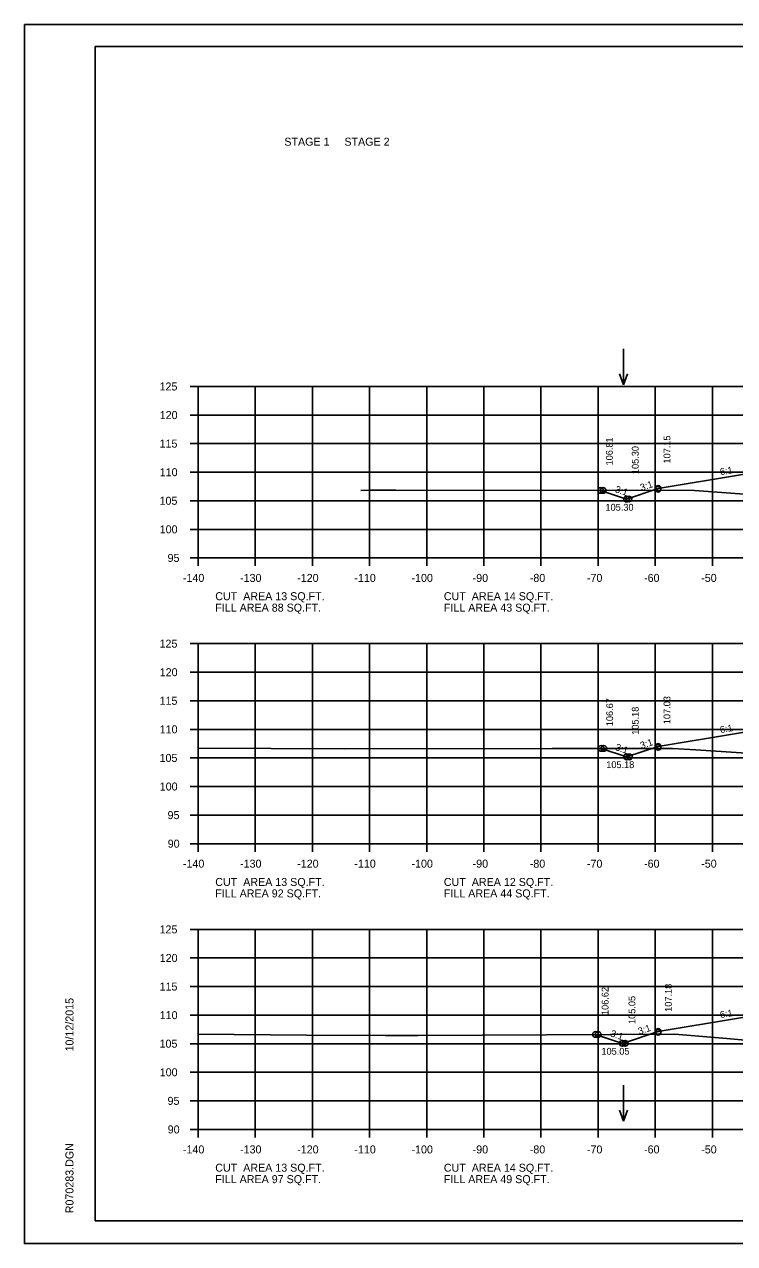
# Model space of a CAD drawing. Extents: x 1175611 to 1176402, y -433344 to -416213.
# Drawn here: x 1175610.6 to 1175734.9, y -425023.4 to -424810 of the extents above; entities that cross this region are included whole.
import ezdxf

# ---------------------------------------------------------------- set-up
doc = ezdxf.new("R2010")
doc.units = 0
for name, color, linetype in [('Default', 7, 'Continuous'), ('R_Axis', 7, 'Continuous'), ('R_Axis Annot', 7, 'Continuous'), ('R_Border', 7, 'Continuous'), ('R_Exist Surface', 7, 'Continuous'), ('R_Fin Surface', 7, 'Continuous'), ('R_Grid', 7, 'Continuous'), ('R_No Plot', 7, 'Continuous'), ('R_Water Annot', 7, 'Continuous'), ('R_Xsect Elev', 7, 'Continuous'), ('R_Xsect Slope', 7, 'Continuous')]:
    doc.layers.add(name, color=color, linetype=linetype)

msp = doc.modelspace()

# ---------------------------------------------------------------- linework, layer by layer
at = {"layer": 'R_Axis'}
for p, q in [((1175639.57, -424873.37), (1175640.97, -424873.37)), ((1175640.97, -424903.37), (1175640.97, -424873.37)), ((1175639.57, -424878.37), (1175640.97, -424878.37)), ((1175639.57, -424883.37), (1175640.97, -424883.37)), ((1175639.57, -424888.37), (1175640.97, -424888.37)), ((1175639.57, -424893.37), (1175640.97, -424893.37)), ((1175639.57, -424898.37), (1175640.97, -424898.37)), ((1175639.57, -424903.37), (1175640.97, -424903.37)), ((1175640.97, -424903.37), (1175920.97, -424903.37)), ((1175640.97, -424904.77), (1175640.97, -424903.37)), ((1175650.97, -424904.77), (1175650.97, -424903.37)), ((1175660.97, -424904.77), (1175660.97, -424903.37)), ((1175670.97, -424904.77), (1175670.97, -424903.37)), ((1175680.97, -424904.77), (1175680.97, -424903.37)), ((1175690.97, -424904.77), (1175690.97, -424903.37)), ((1175700.97, -424904.77), (1175700.97, -424903.37)), ((1175710.97, -424904.77), (1175710.97, -424903.37)), ((1175720.97, -424904.77), (1175720.97, -424903.37)), ((1175730.97, -424904.77), (1175730.97, -424903.37)), ((1175639.57, -424918.37), (1175640.97, -424918.37)), ((1175640.97, -424953.37), (1175640.97, -424918.37)), ((1175639.57, -424923.37), (1175640.97, -424923.37)), ((1175639.57, -424928.37), (1175640.97, -424928.37)), ((1175639.57, -424933.37), (1175640.97, -424933.37)), ((1175639.57, -424938.37), (1175640.97, -424938.37)), ((1175639.57, -424943.37), (1175640.97, -424943.37)), ((1175639.57, -424948.37), (1175640.97, -424948.37)), ((1175639.57, -424953.37), (1175640.97, -424953.37)), ((1175640.97, -424953.37), (1175920.97, -424953.37)), ((1175640.97, -424954.77), (1175640.97, -424953.37)), ((1175650.97, -424954.77), (1175650.97, -424953.37)), ((1175660.97, -424954.77), (1175660.97, -424953.37)), ((1175670.97, -424954.77), (1175670.97, -424953.37)), ((1175680.97, -424954.77), (1175680.97, -424953.37)), ((1175690.97, -424954.77), (1175690.97, -424953.37)), ((1175700.97, -424954.77), (1175700.97, -424953.37)), ((1175710.97, -424954.77), (1175710.97, -424953.37)), ((1175720.97, -424954.77), (1175720.97, -424953.37)), ((1175730.97, -424954.77), (1175730.97, -424953.37)), ((1175639.57, -424968.37), (1175640.97, -424968.37)), ((1175640.97, -425003.37), (1175640.97, -424968.37)), ((1175639.57, -424973.37), (1175640.97, -424973.37)), ((1175639.57, -424978.37), (1175640.97, -424978.37)), ((1175639.57, -424983.37), (1175640.97, -424983.37)), ((1175639.57, -424988.37), (1175640.97, -424988.37)), ((1175639.57, -424993.37), (1175640.97, -424993.37)), ((1175639.57, -424998.37), (1175640.97, -424998.37)), ((1175639.57, -425003.37), (1175640.97, -425003.37)), ((1175640.97, -425003.37), (1175920.97, -425003.37)), ((1175640.97, -425004.77), (1175640.97, -425003.37)), ((1175650.97, -425004.77), (1175650.97, -425003.37)), ((1175660.97, -425004.77), (1175660.97, -425003.37)), ((1175670.97, -425004.77), (1175670.97, -425003.37)), ((1175680.97, -425004.77), (1175680.97, -425003.37)), ((1175690.97, -425004.77), (1175690.97, -425003.37)), ((1175700.97, -425004.77), (1175700.97, -425003.37)), ((1175710.97, -425004.77), (1175710.97, -425003.37)), ((1175720.97, -425004.77), (1175720.97, -425003.37)), ((1175730.97, -425004.77), (1175730.97, -425003.37))]:
    msp.add_line(p, q, dxfattribs=at)
at = {"layer": 'R_Border'}
for p, q in [((1175622.97, -424813.91), (1175939.15, -424813.91)), ((1175622.97, -425019.37), (1175622.97, -424813.91)), ((1175622.97, -425019.37), (1175622.97, -425019.37)), ((1175939.15, -425019.37), (1175622.97, -425019.37))]:
    msp.add_line(p, q, dxfattribs=at)
at = {"layer": 'R_Exist Surface'}
for points in [[(1175669.46, -424891.55), (1175671.18, -424891.52), (1175672.41, -424891.51), (1175675.54, -424891.51), (1175727.83, -424891.58), (1175739.76, -424892.43)], [(1175640.97, -424936.64), (1175666.53, -424936.75), (1175702.92, -424936.7), (1175723.96, -424936.7), (1175728.05, -424936.95), (1175743.05, -424937.92)], [(1175640.97, -424986.72), (1175659.91, -424986.85), (1175673.71, -424986.93), (1175679.41, -424986.91), (1175724.37, -424986.68), (1175733.48, -424987.44), (1175741.88, -424988.2)]]:
    msp.add_lwpolyline(points, dxfattribs=at)
at = {"layer": 'R_Fin Surface'}
for points in [[(1175711.41, -424891.56), (1175715.94, -424893.07), (1175721.47, -424891.22), (1175735.2, -424888.94), (1175743.47, -424887.56), (1175749.47, -424887.32), (1175751.47, -424887.28), (1175780.97, -424886.69), (1175810.47, -424887.28), (1175812.47, -424887.32), (1175818.47, -424887.56), (1175823.75, -424888.88), (1175840.47, -424893.06), (1175840.83, -424893.18), (1175845.76, -424891.53)], [(1175711.49, -424936.7), (1175715.96, -424938.19), (1175721.47, -424936.35), (1175735.2, -424934.07), (1175743.47, -424932.69), (1175749.47, -424932.45), (1175751.47, -424932.41), (1175780.97, -424931.82), (1175810.47, -424932.41), (1175812.47, -424932.45), (1175818.47, -424932.69), (1175823.75, -424934.01), (1175840.47, -424938.19), (1175840.87, -424938.32), (1175844.54, -424937.1)], [(1175710.51, -424986.75), (1175715.21, -424988.31), (1175721.47, -424986.23), (1175735.2, -424983.94), (1175743.47, -424982.56), (1175749.47, -424982.32), (1175751.47, -424982.28), (1175780.97, -424981.69), (1175810.47, -424982.28), (1175812.47, -424982.32), (1175818.47, -424982.56), (1175823.75, -424983.88), (1175840.47, -424988.06), (1175841.68, -424988.46), (1175845.03, -424987.35)]]:
    msp.add_lwpolyline(points, dxfattribs=at)
at = {"layer": 'R_Grid'}
for p, q in [((1175640.97, -424873.37), (1175920.97, -424873.37)), ((1175640.97, -424903.37), (1175640.97, -424873.37)), ((1175650.97, -424903.37), (1175650.97, -424873.37)), ((1175660.97, -424903.37), (1175660.97, -424873.37)), ((1175670.97, -424903.37), (1175670.97, -424873.37)), ((1175680.97, -424903.37), (1175680.97, -424873.37)), ((1175690.97, -424903.37), (1175690.97, -424873.37)), ((1175700.97, -424903.37), (1175700.97, -424873.37)), ((1175710.97, -424903.37), (1175710.97, -424873.37)), ((1175720.97, -424903.37), (1175720.97, -424873.37)), ((1175730.97, -424903.37), (1175730.97, -424873.37)), ((1175640.97, -424878.37), (1175920.97, -424878.37)), ((1175640.97, -424883.37), (1175920.97, -424883.37)), ((1175640.97, -424888.37), (1175920.97, -424888.37)), ((1175640.97, -424893.37), (1175920.97, -424893.37)), ((1175640.97, -424898.37), (1175920.97, -424898.37)), ((1175640.97, -424903.37), (1175920.97, -424903.37)), ((1175640.97, -424918.37), (1175920.97, -424918.37)), ((1175640.97, -424953.37), (1175640.97, -424918.37)), ((1175650.97, -424953.37), (1175650.97, -424918.37)), ((1175660.97, -424953.37), (1175660.97, -424918.37)), ((1175670.97, -424953.37), (1175670.97, -424918.37)), ((1175680.97, -424953.37), (1175680.97, -424918.37)), ((1175690.97, -424953.37), (1175690.97, -424918.37)), ((1175700.97, -424953.37), (1175700.97, -424918.37)), ((1175710.97, -424953.37), (1175710.97, -424918.37)), ((1175720.97, -424953.37), (1175720.97, -424918.37)), ((1175730.97, -424953.37), (1175730.97, -424918.37)), ((1175640.97, -424923.37), (1175920.97, -424923.37)), ((1175640.97, -424928.37), (1175920.97, -424928.37)), ((1175640.97, -424933.37), (1175920.97, -424933.37)), ((1175640.97, -424938.37), (1175920.97, -424938.37)), ((1175640.97, -424943.37), (1175920.97, -424943.37)), ((1175640.97, -424948.37), (1175920.97, -424948.37)), ((1175640.97, -424953.37), (1175920.97, -424953.37)), ((1175640.97, -424968.37), (1175920.97, -424968.37)), ((1175640.97, -425003.37), (1175640.97, -424968.37)), ((1175650.97, -425003.37), (1175650.97, -424968.37)), ((1175660.97, -425003.37), (1175660.97, -424968.37)), ((1175670.97, -425003.37), (1175670.97, -424968.37)), ((1175680.97, -425003.37), (1175680.97, -424968.37)), ((1175690.97, -425003.37), (1175690.97, -424968.37)), ((1175700.97, -425003.37), (1175700.97, -424968.37)), ((1175710.97, -425003.37), (1175710.97, -424968.37)), ((1175720.97, -425003.37), (1175720.97, -424968.37)), ((1175730.97, -425003.37), (1175730.97, -424968.37)), ((1175640.97, -424973.37), (1175920.97, -424973.37)), ((1175640.97, -424978.37), (1175920.97, -424978.37)), ((1175640.97, -424983.37), (1175920.97, -424983.37)), ((1175640.97, -424988.37), (1175920.97, -424988.37)), ((1175640.97, -424993.37), (1175920.97, -424993.37)), ((1175640.97, -424998.37), (1175920.97, -424998.37)), ((1175640.97, -425003.37), (1175920.97, -425003.37))]:
    msp.add_line(p, q, dxfattribs=at)
at = {"layer": 'R_No Plot'}
for p, q in [((1175610.57, -424810.01), (1175943.91, -424810.01)), ((1175610.57, -425023.35), (1175943.91, -425023.35))]:
    msp.add_line(p, q, dxfattribs=at)
msp.add_lwpolyline([(1175610.57, -424810.01), (1175943.91, -424810.01), (1175943.91, -425023.35), (1175610.57, -425023.35)], close=True, dxfattribs=at)
for centre in [(1175711.41, -424891.56), (1175711.41, -424891.56), (1175711.86, -424891.56), (1175721.47, -424891.22), (1175721.47, -424891.35), (1175715.94, -424893.07), (1175716.35, -424893.06), (1175711.49, -424936.7), (1175711.49, -424936.7), (1175711.98, -424936.7), (1175721.47, -424936.35), (1175721.47, -424936.51), (1175715.96, -424938.19), (1175716.44, -424938.19), (1175710.51, -424986.75), (1175710.51, -424986.75), (1175710.98, -424986.74), (1175721.47, -424986.23), (1175721.47, -424986.38), (1175715.21, -424988.31), (1175715.68, -424988.31)]:
    msp.add_circle(centre, 0.5, dxfattribs=at)
at = {"layer": 'R_Water Annot'}
for p, q in [((1175715.39, -424866.78), (1175715.39, -424873.06)), ((1175715.39, -424873.06), (1175714.69, -424871.14)), ((1175715.39, -424873.06), (1175716.09, -424871.14)), ((1175715.39, -424995.63), (1175715.39, -425001.92)), ((1175715.39, -425001.92), (1175714.69, -424999.99)), ((1175715.39, -425001.92), (1175716.09, -424999.99))]:
    msp.add_line(p, q, dxfattribs=at)

# ---------------------------------------------------------------- texts
at = {"layer": 'Default'}
for s, p in [('STAGE 1     STAGE 2', (1175656.06, -424831.24)), ('CUT  AREA 13 SQ.FT.', (1175643.97, -424910.77)), ('CUT  AREA 14 SQ.FT.', (1175683.97, -424910.77)), ('FILL AREA 88 SQ.FT.', (1175643.97, -424912.77)), ('FILL AREA 43 SQ.FT.', (1175683.97, -424912.77)), ('CUT  AREA 13 SQ.FT.', (1175643.97, -424960.77)), ('CUT  AREA 12 SQ.FT.', (1175683.97, -424960.77)), ('FILL AREA 92 SQ.FT.', (1175643.97, -424962.77)), ('FILL AREA 44 SQ.FT.', (1175683.97, -424962.77)), ('CUT  AREA 13 SQ.FT.', (1175643.97, -425010.77)), ('CUT  AREA 14 SQ.FT.', (1175683.97, -425010.77)), ('FILL AREA 97 SQ.FT.', (1175643.97, -425012.77)), ('FILL AREA 49 SQ.FT.', (1175683.97, -425012.77))]:
    msp.add_text(s, height=1.4, dxfattribs=at).set_placement(p)
at = {"layer": 'R_Axis Annot'}
for s, p in [('125', (1175634.22, -424874.07)), ('120', (1175634.25, -424879.07)), ('115', (1175634.22, -424884.07)), ('110', (1175634.25, -424889.07)), ('105', (1175634.22, -424894.07)), ('100', (1175634.25, -424899.07)), ('95', (1175635.62, -424904.07)), ('-140', (1175638.31, -424907.57)), ('-130', (1175648.31, -424907.57)), ('-120', (1175658.31, -424907.57)), ('-110', (1175668.31, -424907.57)), ('-100', (1175678.31, -424907.57)), ('-90', (1175689.01, -424907.57)), ('-80', (1175699.01, -424907.57)), ('-70', (1175709.01, -424907.57)), ('-60', (1175719.01, -424907.57)), ('-50', (1175729.01, -424907.57)), ('125', (1175634.22, -424919.07)), ('120', (1175634.25, -424924.07)), ('115', (1175634.22, -424929.07)), ('110', (1175634.25, -424934.07)), ('105', (1175634.22, -424939.07)), ('100', (1175634.25, -424944.07)), ('95', (1175635.62, -424949.07)), ('90', (1175635.65, -424954.07)), ('-140', (1175638.31, -424957.57)), ('-130', (1175648.31, -424957.57)), ('-120', (1175658.31, -424957.57)), ('-110', (1175668.31, -424957.57)), ('-100', (1175678.31, -424957.57)), ('-90', (1175689.01, -424957.57)), ('-80', (1175699.01, -424957.57)), ('-70', (1175709.01, -424957.57)), ('-60', (1175719.01, -424957.57)), ('-50', (1175729.01, -424957.57)), ('125', (1175634.22, -424969.07)), ('120', (1175634.25, -424974.07)), ('115', (1175634.22, -424979.07)), ('110', (1175634.25, -424984.07)), ('105', (1175634.22, -424989.07)), ('100', (1175634.25, -424994.07)), ('95', (1175635.62, -424999.07)), ('90', (1175635.65, -425004.07)), ('-140', (1175638.31, -425007.57)), ('-130', (1175648.31, -425007.57)), ('-120', (1175658.31, -425007.57)), ('-110', (1175668.31, -425007.57)), ('-100', (1175678.31, -425007.57)), ('-90', (1175689.01, -425007.57)), ('-80', (1175699.01, -425007.57)), ('-70', (1175709.01, -425007.57)), ('-60', (1175719.01, -425007.57)), ('-50', (1175729.01, -425007.57))]:
    msp.add_text(s, height=1.4, dxfattribs=at).set_placement(p)
at = {"layer": 'R_Border'}
for s, p in [('10/12/2015', (1175619.16, -424989.73)), ('R070283.DGN', (1175619.16, -425018.04))]:
    msp.add_text(s, height=1.4, rotation=90, dxfattribs=at).set_placement(p)
at = {"layer": 'R_Xsect Elev'}
for s, p in [('106.81', (1175713.54, -424887.19)), ('107.15', (1175723.62, -424886.85)), ('105.30', (1175718.07, -424888.7)), ('107.03', (1175723.62, -424932.46)), ('106.67', (1175713.59, -424932.82)), ('105.18', (1175718.07, -424934.31)), ('106.62', (1175712.79, -424983.35)), ('107.18', (1175723.86, -424982.79)), ('105.05', (1175717.49, -424984.92))]:
    msp.add_text(s, height=1.2, rotation=90, dxfattribs=at).set_placement(p)
for s, p in [('105.30', (1175712.26, -424895.11)), ('105.18', (1175712.39, -424940.15)), ('105.05', (1175711.55, -424990.3))]:
    msp.add_text(s, height=1.2, dxfattribs=at).set_placement(p)
at = {"layer": 'R_Xsect Slope'}
for s, rotation, p in [('6:1', 9.4623, (1175732.39, -424888.9)), ('3:1', 341.5651, (1175713.83, -424891.84)), ('3:1', 18.4349, (1175718.55, -424891.67)), ('6:1', 9.4623, (1175732.39, -424934.03)), ('3:1', 341.5651, (1175713.88, -424936.97)), ('3:1', 18.4349, (1175718.56, -424936.8)), ('6:1', 9.4623, (1175732.39, -424983.9)), ('3:1', 18.4349, (1175718.18, -424986.8)), ('3:1', 341.5651, (1175713.02, -424987.06))]:
    msp.add_text(s, height=1.2, rotation=rotation, dxfattribs=at).set_placement(p)

doc.saveas('drawing.dxf')
